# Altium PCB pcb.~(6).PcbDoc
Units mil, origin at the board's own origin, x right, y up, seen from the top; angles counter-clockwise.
Board outline 2165 x 2075 mil, 2 copper layers (Top Layer, Bottom Layer); 12 components, 10 nets, 37 pads, 0 vias.
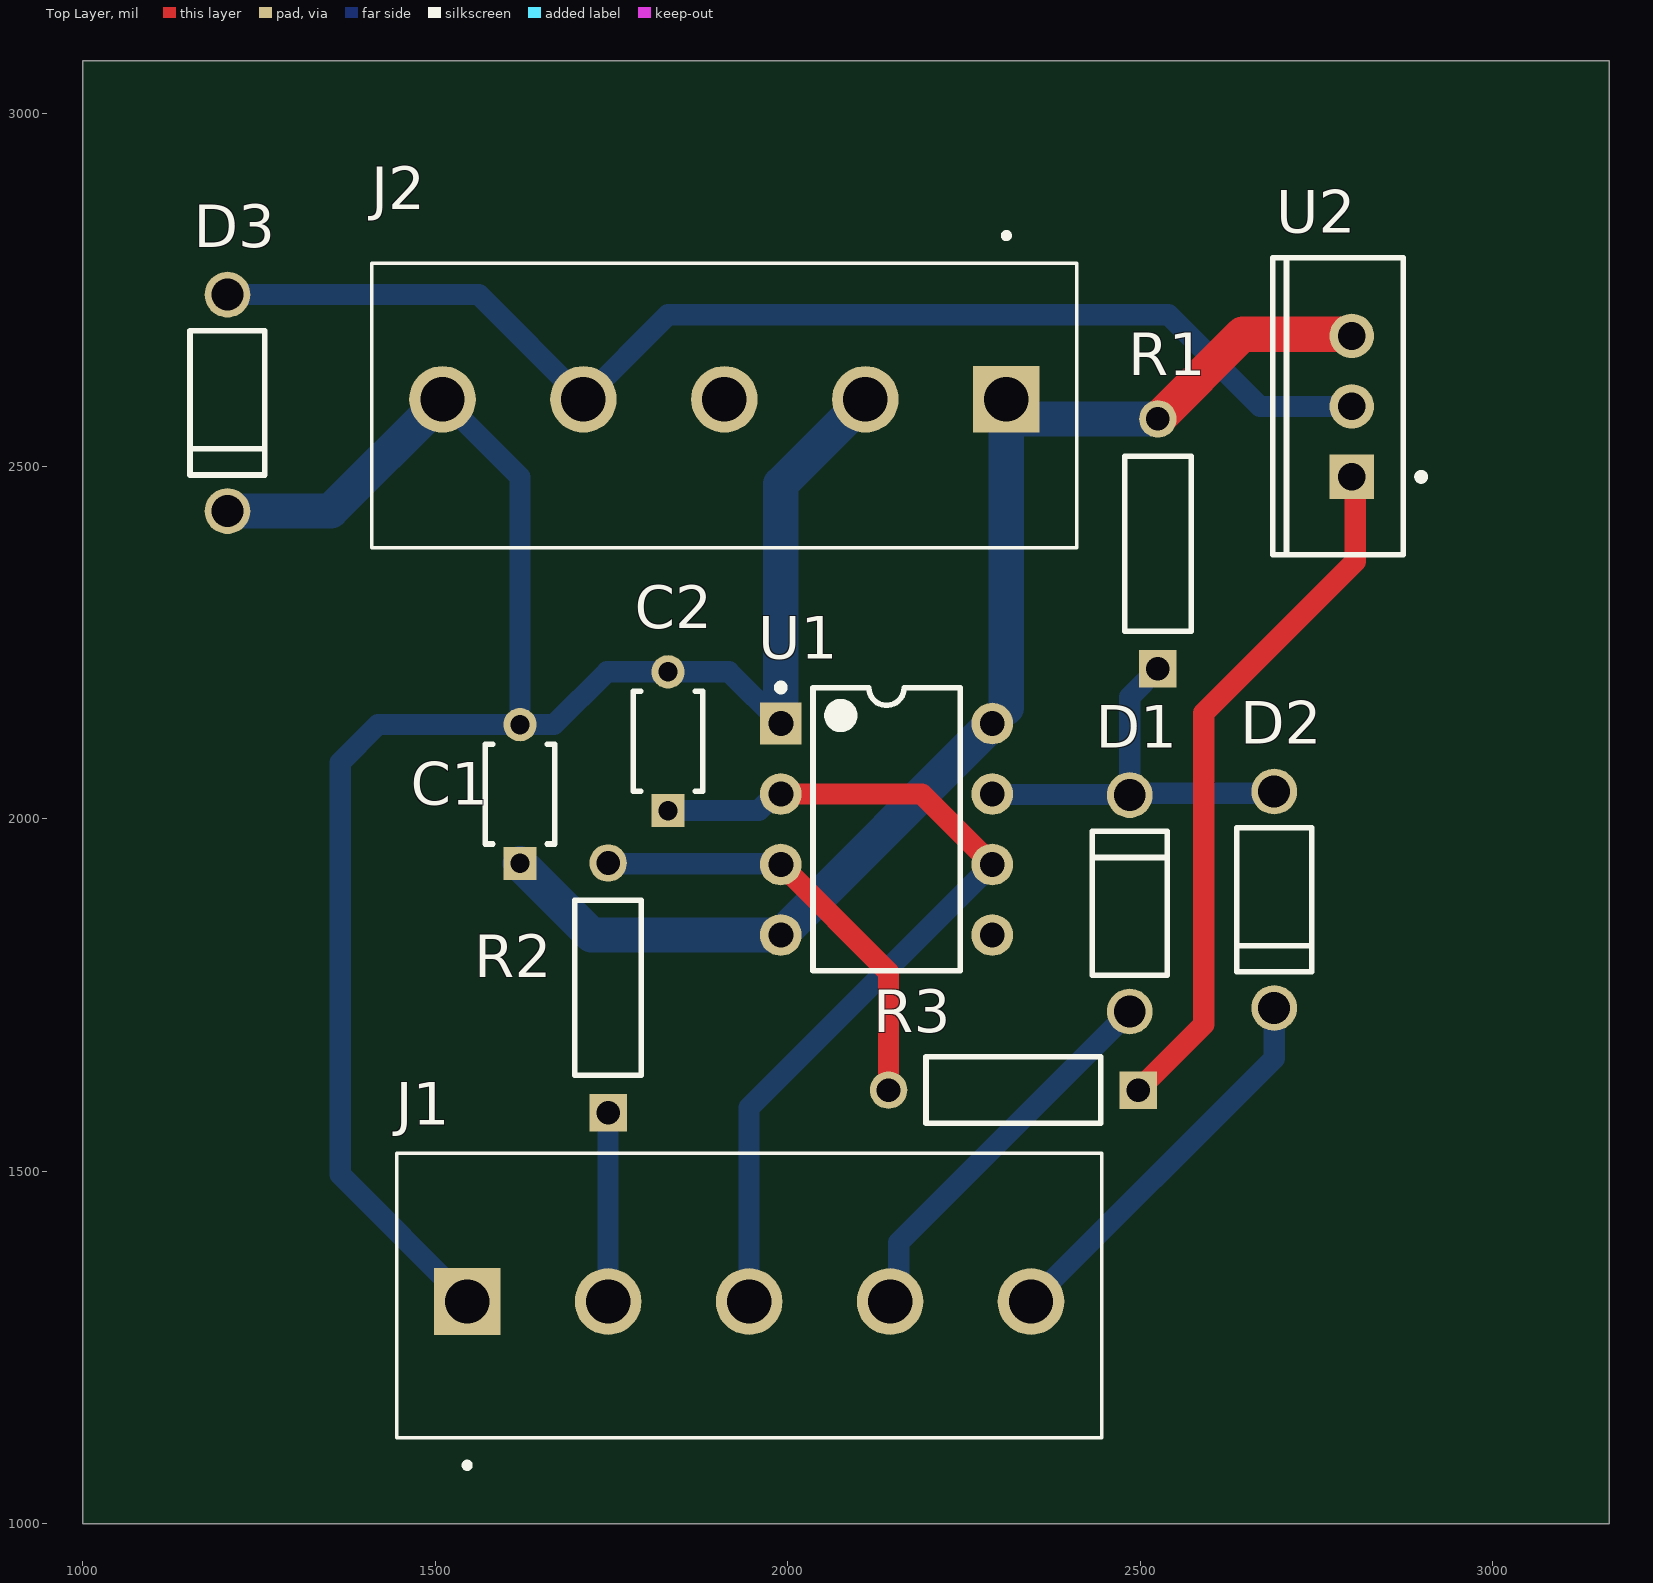
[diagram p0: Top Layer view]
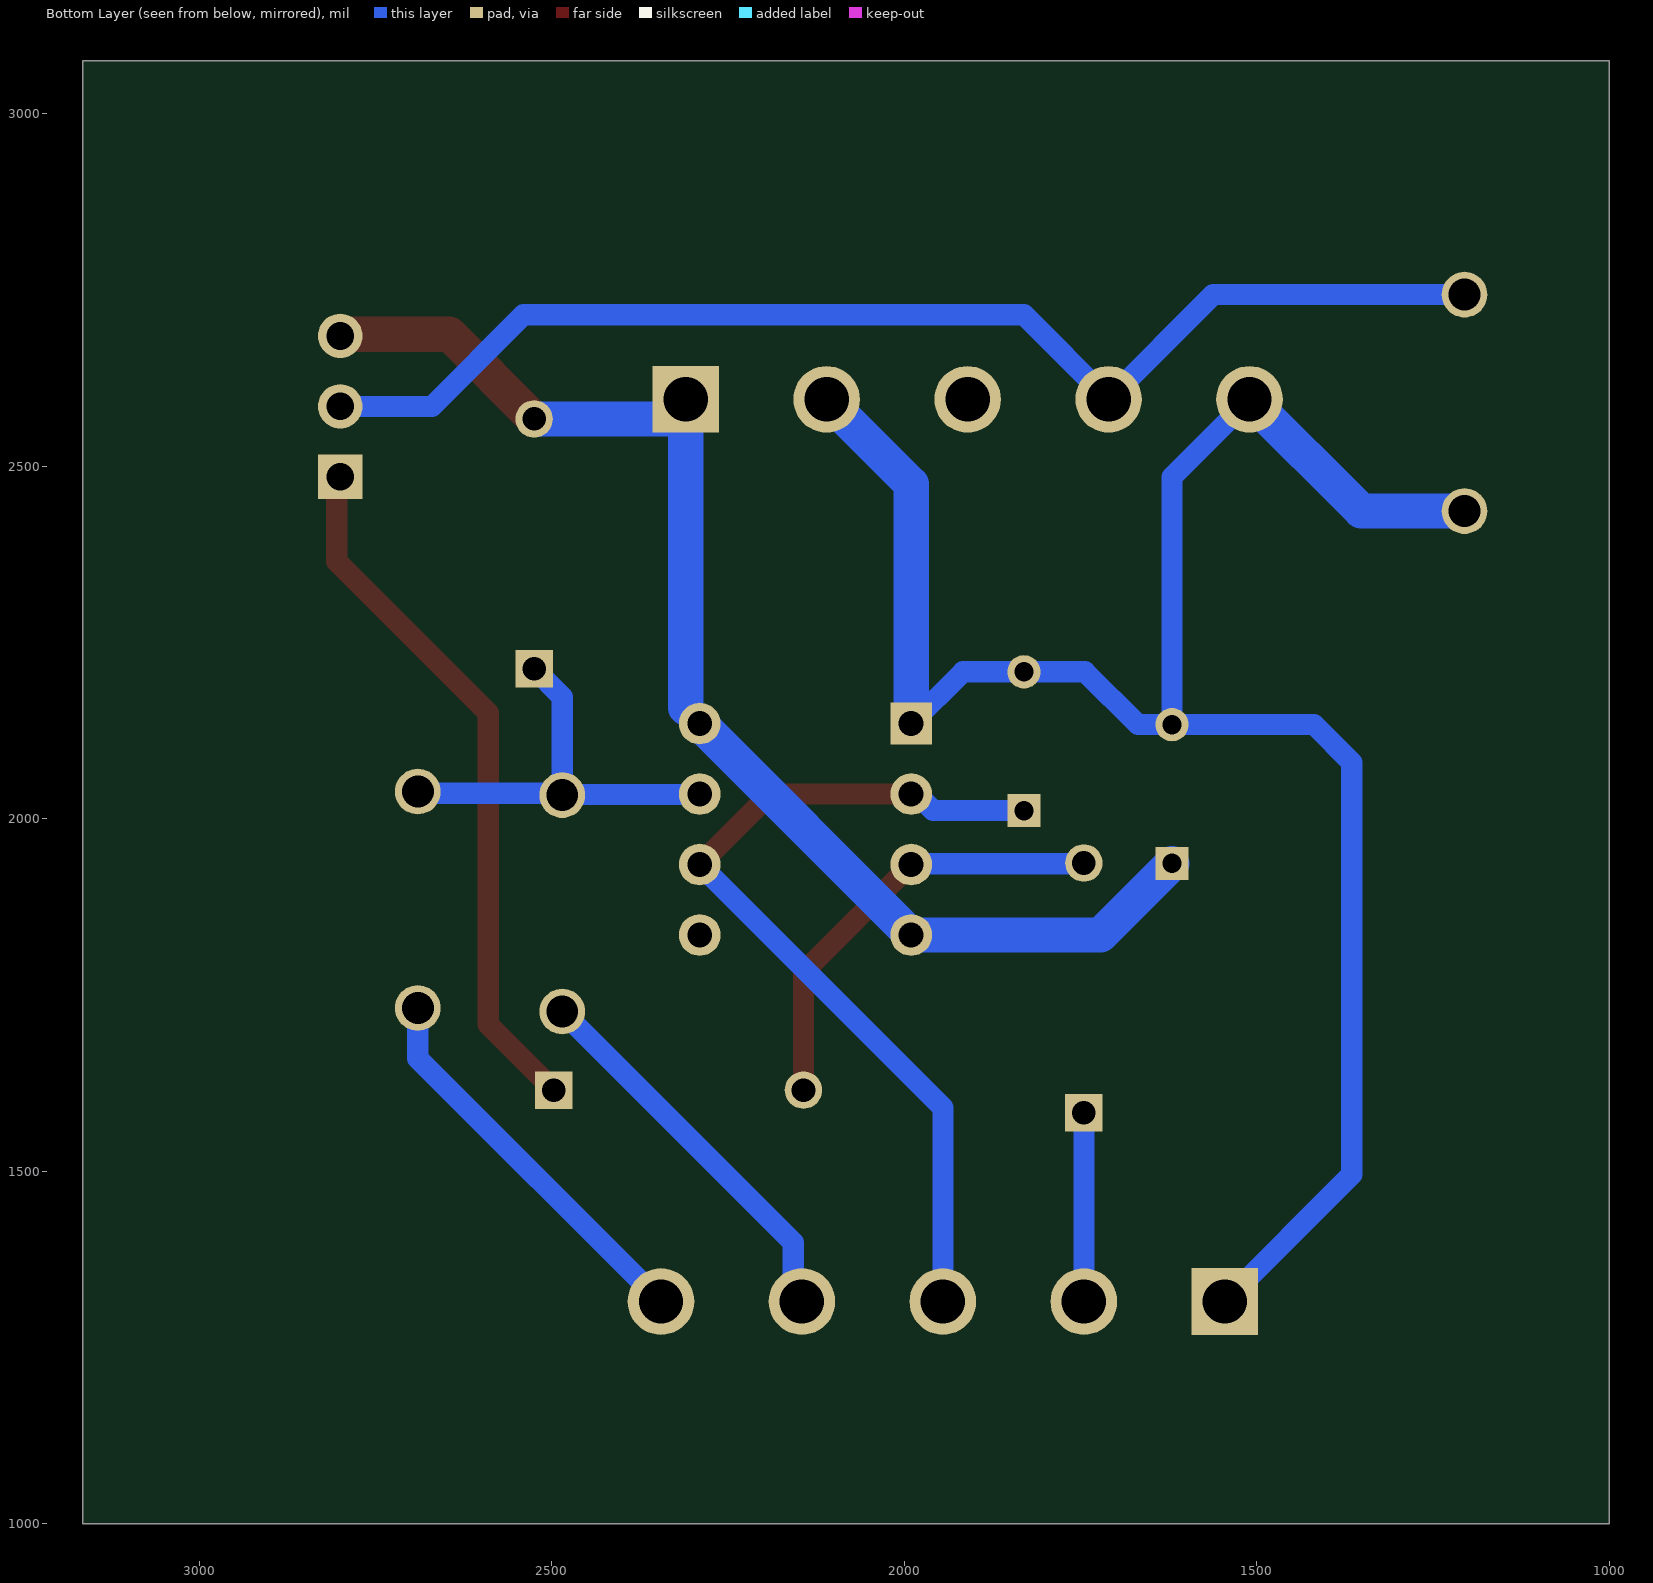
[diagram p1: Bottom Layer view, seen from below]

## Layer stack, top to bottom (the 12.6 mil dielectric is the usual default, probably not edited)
Top Solder: solder mask 0.4, Solder Resist, Dk 3.5
Top Layer: signal copper 1.4
Dielectric 1: dielectric 12.6, FR-4, Dk 4.8
Bottom Layer: signal copper 1.4
Bottom Solder: solder mask 0.4, Solder Resist, Dk 3.5

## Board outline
1000,1000 3165,1000 3165,3075 1000,3075

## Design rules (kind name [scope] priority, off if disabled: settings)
Clearance [All] p1: gap=10 ignorepadtopadclearanceinfootprint=FALSE except(0: Arc-Hole Track-Hole SMDPad-Hole THPad-Hole Via-Hole Fill-Hole Poly-Hole Region-Hole Text-Hole)
PolygonConnect [All] p1: connectstyle=Relief reliefconductorwidth=10 reliefentries=4 polygonreliefangle="90 Angle" airgapwidth=10
RoutingVias [All] p1: holewidth=30 width=50 viastyle="Through Hole" minholewidth=26 minwidth=36 maxholewidth=50 maxwidth=70
SolderMaskExpansion [All] p1: expansion=4 istentingtop=FALSE
Width [All] p1: maxlimit=50 minlimit=15 preferedwidth=35
30 further rules are at their usual default settings.

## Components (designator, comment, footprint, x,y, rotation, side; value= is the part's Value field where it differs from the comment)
C1 "RCER71H103K0K1H03B" FP-RCE0K1-MFG 1620,2035 r90 top
C2 "RCER71H103K0K1H03B" FP-RCE0K1-MFG 1830,2110 r90 top
D1 "1N4007" FAIR-DO-41-2 2485,1880 r90 top
D2 "1N4007" FAIR-DO-41-2 2690,1885 r270 top
D3 "1N4007" FAIR-DO-41-2 1205,2590 r270 top
J1 "TB007-508-05BE" CUI_TB007-508-05BE 1545,1315 r0 top
J2 "TB007-508-05BE" CUI_TB007-508-05BE 2310,2595 r180 top
R1 "MFR-25FBF52-1K" RESA60-630X240 2525,2390 r90 top
R2 "MFR-25FBF52-1K" RESA60-630X240 1745,1760 r90 top
R3 "MFR-25FBF52-1K" RESA60-630X240 2320,1615 r180 top
U1 "NE555P" P0008A 2140,1985 r0 top
U2 "LM395T/NOPB" NDE0003A 2800,2585 r90 top

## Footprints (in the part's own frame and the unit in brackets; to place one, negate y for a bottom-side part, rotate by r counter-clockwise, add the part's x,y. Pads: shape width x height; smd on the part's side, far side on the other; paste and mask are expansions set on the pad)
CUI_TB007-508-05BE [mm]
  rect 2.4x2.4 hole 1.6: 1(0,0)
  round 2.4 hole 1.6: 2(5.08,0) 3(10.16,0) 4(15.24,0) 5(20.32,0)
  silkscreen extent -2.54,-6 22.86,5.35
FAIR-DO-41-2 [mm] "THD, 2-Leads, Body 5.2x2.72mm, Pin Spacing 7.8mm"
  round 1.65 hole 1.15: 1(-3.9,0) 2(3.9,0)
  silkscreen extent -2.6,-1.35 2.6,1.35, body extent -4.29,-1.17 4.29,1.17, height 2.35
FP-RCE0K1-MFG [mm]
  rect 1.2x1.2 hole 0.7 paste-1000 mask+0: 1(-2.5,0)
  round 1.2 hole 0.7 paste-1000 mask+0: 2(2.5,0)
  silkscreen extent -1.8,-1.25 1.8,1.25, body extent -3.2,-1.35 3.2,1.35, height 0.25
NDE0003A [mm] "FM, 3-Leads, Body 10.7x4.7mm, Pitch 2.54mm"
  rect 1.6x1.6 hole 1: 1(-2.54,0)
  round 1.6 hole 1: 2(0,0) 3(2.54,0)
  silkscreen extent -5.35,-2.63 5.35,2.85, body extent -5.4,-1.9 5.4,2.9, height 19.4
P0008A [mm] "DIP, 8-Leads, Body 10.15x6.6mm, Pitch 2.54mm"
  rect 1.5x1.5 hole 0.9: 1(-3.81,3.81)
  round 1.5 hole 0.9: 2(-3.81,1.27) 3(-3.81,-1.27) 4(-3.81,-3.81) 5(3.81,-3.81) 6(3.81,-1.27) 7(3.81,1.27) 8(3.81,3.81)
  silkscreen extent -3.93,-5.1 2.65,5.23, body extent -3.95,-5.07 3.95,5.07, height 5.08
RESA60-630X240 [mm] "Axial Resistor, 2-Leads, Dia 2.4mm, Body Length 6.3mm"
  rect 1.35x1.35 hole 0.85: 1(-4.5,0)
  round 1.35 hole 0.85: 2(4.5,0)
  silkscreen extent -3.15,-1.2 3.15,1.2, body extent -3.15,-1.2 3.15,1.2, height 2.4

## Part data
C1 C2: library part CMP-06035-044411-1, "Cap Ceramic 10nF 50V X7R ±10% Radial 5mm +125°C Automotive Bulk", Capacitance=10nF, Case/Package=Radial, Dielectric=X7R, Max Operating Temperature=125°C, Min Operating Temperature=-55°C, Package Quantity=500, Ratings=AEC-Q200, Resistor Type=Ceramic, Tolerance=10%, Voltage Rating=50V
D1 D2 D3: library part CMP-004-00007-1, "General Purpose Rectifier, 1.1 V, 1.0 A, -55 to 175 degC, 2-Pin DO-41, RoHS, Tape and Reel", Case/Package=DO-41-2, Forward Current=1A, Forward Voltage=1.1V, Manufacturer=Fairchild, Max Operating Temperature=175°C, Max Surge Current=30A, Min Operating Temperature=-55°C, Package Description="2-Pin Axial Lead, Dia 2.375 mm, Body Length 4.63 mm", Package Quantity=5000, Package Version="Rev. 2, 09/2008", Peak Reverse Current=5uA
J1 J2: Package=None
R1 R2 R3: library part CMP-1659-00075-1, "Axial Resistor, 1 KOhm, +/- 1%, 250 mW, -55 to 155 degC, 2-Pin THD, RoHS, Bulk", Case\Package=Axial, Max Operating Temperature="155 degC", Min Operating Temperature="-55 degC", Package Quantity=200, Power Rating="250 mW", Resistance="10 kohm", Tolerance=1%, Voltage Rating="250 V"
U1: library part CMP-2000-04954-1, "Precision Timer, 4.5 to 16 V, 0 to 70 degC, 8-Pin DIP, Pb-Free, Tube", Manufacturer=TexasInstruments, Maximum High Level Output Current=-200mA, Maximum Low Level Output Current=200mA, Operating Supply Voltage=5, Package=8PDIP, Package Description="8-Pin Double In-line Package, Body 9.59 x 6.35 mm, Pitch 2.54 mm", Package Reference=P8
U2: library part CMP-0063-01416-3, "Ultra Reliable Power Transistor, 3-pin TO-220, Pb-Free", Manufacturer="Texas Instruments", PackageTopMarking=NSUZXYTTE#*LM395T, PowerWise=N

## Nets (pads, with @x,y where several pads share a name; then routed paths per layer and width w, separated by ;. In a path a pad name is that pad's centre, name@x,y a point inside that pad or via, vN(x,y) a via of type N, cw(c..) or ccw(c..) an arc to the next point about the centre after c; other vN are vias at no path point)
GND: C1.2 C2.2 D3.2 J1.1 J2.2 J2.5 U1.1 | length 2959.8
  Top Layer w50: J2.2@2110,2582.96 J2.2
  Bottom Layer w30: J2.5 1620,2485 C1.2 ; J1.1 1365,1495 1365,2080 1418.43,2133.43 C1.2 ; U1.1 1916.57,2208.43 C2.2 1743.43,2208.43 1668.43,2133.43 C1.2
  Bottom Layer w50: D3.2 1351.46,2436.46 J2.5 ; U1.1 1990,2475 J2.2 J2.2@2110,2582.96
LED_IN: J1.2 R2.1 | length 282
  Bottom Layer w30: R2.1 J1.2 J1.2@1755,1325
NetC2_1: C2.1 J1.3 U1.2 U1.6 | length 1274
  Top Layer w30: U1.2 2190,2035 U1.6
  Bottom Layer w30: C2.1 1958.71,2011.57 1982.14,2035 U1.2 ; J1.3 1945,1590 U1.6
NetD1_1: D1.1 J1.4 | length 552.3
  Bottom Layer w30: J1.4 2157.34,1327.34 2157.34,1398.8 D1.1
NetD1_2: D1.2 D2.1 R1.1 U1.7 | length 598.5
  Bottom Layer w30: U1.7 2290.73,2034.27 2484.27,2034.27 D1.2 ; R1.1 2485,2172.83 D1.2 ; D2.1 2687.5,2036.04 2487.5,2036.04 D1.2
NetD2_2: D2.2 J1.5 | length 559.4
  Bottom Layer w30: J1.5 2690,1660 D2.2
NetD3_1: D3.1 J2.4 U2.2 | length 1760.1
  Bottom Layer w30: D3.1 1561.46,2743.54 J2.4 1830,2715 2540,2715 2670,2585 U2.2
NetR2_2: R2.2 R3.2 U1.3 | length 635.5
  Top Layer w30: U1.3 2142.83,1782.17 R3.2
  Bottom Layer w30: R2.2@1751.26,1937.17 R2.2 1746.08,1936.08 1988.92,1936.08 U1.3
NetR3_1: R3.1 U2.1 | length 999.6
  Top Layer w30: R3.1 2590,1707.83 2590,2150 2805,2365 2805,2480 U2.1
VCC: C1.1 J2.1 R1.2 U1.4 U1.8 U2.3 | length 1826.3
  Top Layer w50: R1.2 2645.32,2687.49 2797.51,2687.49 U2.3
  Bottom Layer w50: C1.1 1721.57,1835 U1.4 U1.8 ; 2310,2157.45 J2.1 2337.83,2567.17 R1.2
pads on no net: J2.3 U1.5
